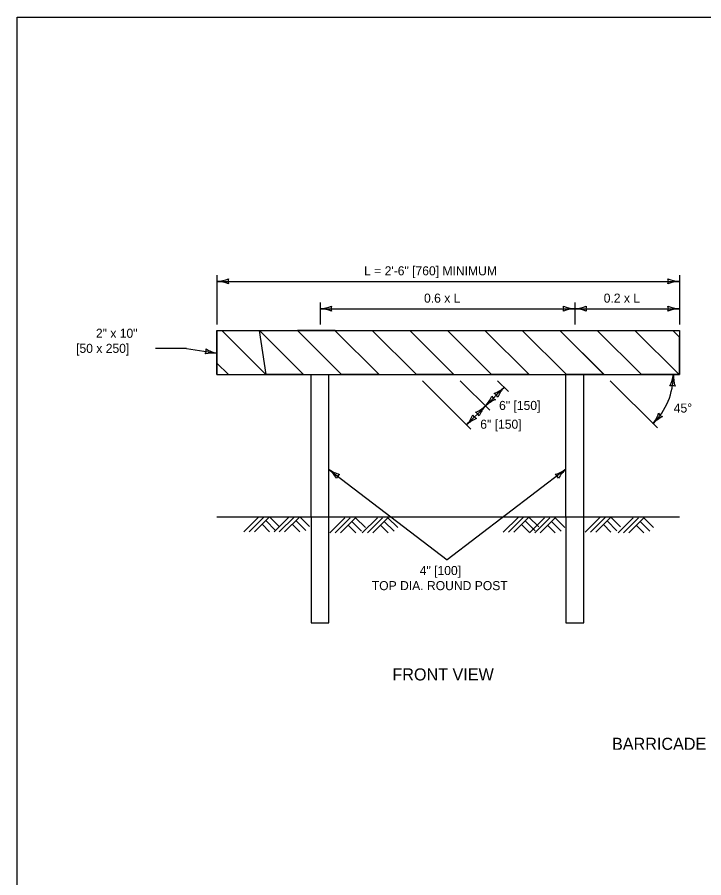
# Model space of a CAD drawing. Extents: x 49991.4 to 50021, y 49987.6 to 50011.4.
# Drawn here: x 49999.38 to 50003.93, y 49993.3 to 49999 of the extents above; entities that cross this region are included whole.
import ezdxf

# ---------------------------------------------------------------- set-up
doc = ezdxf.new("R2010")
doc.units = 0
for name, color, linetype in [('Level 1', 7, 'Continuous'), ('Level 2', 7, 'Continuous'), ('Level 3', 7, 'Continuous'), ('Level 4', 7, 'Continuous')]:
    doc.layers.add(name, color=color, linetype=linetype)

msp = doc.modelspace()

# ---------------------------------------------------------------- linework, layer by layer
at = {"layer": 'Level 1'}
for p, q in [((50000.7069, 49996.9246), (50000.7069, 49996.6317)), ((50000.7069, 49996.7073), (50000.7069, 49996.9246)), ((50000.7069, 49996.9246), (50000.738, 49996.9246)), ((50000.7069, 49996.9246), (50003.7706, 49996.9246)), ((50000.7069, 49996.6317), (50000.7069, 49996.9246)), ((50000.738, 49996.9246), (50000.9865, 49996.9246)), ((50000.738, 49996.9246), (50000.9865, 49996.9246)), ((50000.738, 49996.9246), (50000.9865, 49996.9246)), ((50000.7389, 49996.9246), (50001.031, 49996.6326)), ((50000.7389, 49996.9246), (50001.031, 49996.6326)), ((50001.031, 49996.6326), (50000.7389, 49996.9246)), ((50001.031, 49996.6326), (50000.7389, 49996.9246)), ((50001.031, 49996.6326), (50000.7389, 49996.9246)), ((50001.031, 49996.6326), (50000.7389, 49996.9246)), ((50000.7389, 49996.9246), (50001.031, 49996.6326)), ((50000.9865, 49996.9246), (50001.031, 49996.6326)), ((50000.9879, 49996.9248), (50001.28, 49996.6326)), ((50000.9879, 49996.9248), (50001.28, 49996.6326)), ((50001.2395, 49996.9236), (50001.5316, 49996.6316)), ((50001.2395, 49996.9236), (50001.5316, 49996.6316)), ((50001.5316, 49996.6316), (50001.2395, 49996.9236)), ((50001.5316, 49996.6316), (50001.2395, 49996.9236)), ((50001.2395, 49996.9236), (50001.5316, 49996.6316)), ((50001.489, 49996.9246), (50001.2402, 49996.9246)), ((50001.489, 49996.9246), (50001.2402, 49996.9246)), ((50001.2402, 49996.9246), (50001.489, 49996.9246)), ((50001.4881, 49996.9238), (50001.7802, 49996.6316)), ((50002.0278, 49996.6317), (50001.7353, 49996.9243)), ((50001.7377, 49996.9246), (50001.9842, 49996.9246)), ((50001.9837, 49996.9243), (50002.2731, 49996.6349)), ((50002.5259, 49996.6317), (50002.2333, 49996.9242)), ((50002.2348, 49996.9246), (50002.4817, 49996.9246)), ((50002.4819, 49996.9244), (50002.774, 49996.6322)), ((50003.022, 49996.6319), (50002.7291, 49996.9249)), ((50002.7297, 49996.9246), (50002.9771, 49996.9246)), ((50002.9775, 49996.9249), (50003.2669, 49996.6355)), ((50002.9775, 49996.9249), (50003.2707, 49996.6319)), ((50003.5195, 49996.6317), (50003.2265, 49996.9246)), ((50003.2265, 49996.9246), (50003.4752, 49996.9246)), ((50003.4752, 49996.9246), (50003.7681, 49996.6317)), ((50003.7706, 49996.8802), (50003.7262, 49996.9246)), ((50003.7262, 49996.9246), (50003.7706, 49996.9246)), ((50003.7706, 49996.9246), (50003.7706, 49996.6317)), ((50003.7706, 49996.9246), (50003.7706, 49996.6317)), ((50003.7706, 49996.6317), (50003.7706, 49996.8802)), ((50000.7825, 49996.6317), (50000.7069, 49996.7073)), ((50000.7069, 49996.6355), (50000.7107, 49996.6317)), ((50000.7069, 49996.6317), (50003.7706, 49996.6317)), ((50001.2799, 49996.6317), (50001.0335, 49996.6317)), ((50001.2799, 49996.6317), (50001.0335, 49996.6317)), ((50001.3313, 49995.6901), (50001.3313, 49996.6313)), ((50001.4485, 49995.6901), (50001.4485, 49996.6313)), ((50001.7794, 49996.6317), (50001.5311, 49996.6317)), ((50002.0291, 49996.6317), (50002.0278, 49996.6317)), ((50002.2732, 49996.6317), (50002.0291, 49996.6317)), ((50002.527, 49996.6317), (50002.5259, 49996.6317)), ((50002.7739, 49996.6317), (50002.527, 49996.6317)), ((50003.0188, 49995.6901), (50003.0188, 49996.6311)), ((50003.0224, 49996.6317), (50003.022, 49996.6319)), ((50003.2707, 49996.6317), (50003.0224, 49996.6317)), ((50003.136, 49995.6901), (50003.136, 49996.6311)), ((50003.7681, 49996.6317), (50003.5195, 49996.6317)), ((50000.7069, 49995.6901), (50003.7706, 49995.6901)), ((50000.8849, 49995.5901), (50000.9849, 49995.6901)), ((50000.9199, 49995.5901), (50001.0199, 49995.6901)), ((50000.9549, 49995.5901), (50001.0549, 49995.6901)), ((50001.0302, 49995.6654), (50001.0952, 49995.6004)), ((50001.0549, 49995.6901), (50001.1199, 49995.6251)), ((50001.0849, 49995.5901), (50001.1849, 49995.6901)), ((50001.1199, 49995.5901), (50001.2199, 49995.6901)), ((50001.1549, 49995.5901), (50001.2549, 49995.6901)), ((50001.2302, 49995.6654), (50001.2952, 49995.6004)), ((50001.2549, 49995.6901), (50001.3199, 49995.6251)), ((50001.4547, 49995.5838), (50001.5547, 49995.6838)), ((50001.4897, 49995.5838), (50001.5897, 49995.6838)), ((50001.5247, 49995.5838), (50001.6247, 49995.6838)), ((50001.6, 49995.6591), (50001.665, 49995.5941)), ((50001.6247, 49995.6838), (50001.6897, 49995.6188)), ((50001.6694, 49995.5838), (50001.7694, 49995.6838)), ((50001.7044, 49995.5838), (50001.8044, 49995.6838)), ((50001.7394, 49995.5838), (50001.8394, 49995.6838)), ((50001.8147, 49995.6591), (50001.8797, 49995.5941)), ((50001.8394, 49995.6838), (50001.9044, 49995.6188)), ((50002.6035, 49995.5876), (50002.7035, 49995.6876)), ((50002.6385, 49995.5876), (50002.7385, 49995.6876)), ((50002.6735, 49995.5876), (50002.7735, 49995.6876)), ((50002.7488, 49995.6629), (50002.8138, 49995.5979)), ((50002.7735, 49995.6876), (50002.8385, 49995.6226)), ((50002.7768, 49995.5838), (50002.8768, 49995.6838)), ((50002.8118, 49995.5838), (50002.9118, 49995.6838)), ((50002.8468, 49995.5838), (50002.9468, 49995.6838)), ((50002.9221, 49995.6591), (50002.9871, 49995.5941)), ((50002.9468, 49995.6838), (50003.0118, 49995.6188)), ((50003.1459, 49995.5876), (50003.2459, 49995.6876)), ((50003.1809, 49995.5876), (50003.2809, 49995.6876)), ((50003.2159, 49995.5876), (50003.3159, 49995.6876)), ((50003.2912, 49995.6629), (50003.3562, 49995.5979)), ((50003.3159, 49995.6876), (50003.3809, 49995.6226)), ((50003.3643, 49995.5838), (50003.4643, 49995.6838)), ((50003.3993, 49995.5838), (50003.4993, 49995.6838)), ((50003.4343, 49995.5838), (50003.5343, 49995.6838)), ((50003.5096, 49995.6591), (50003.5746, 49995.5941)), ((50003.5343, 49995.6838), (50003.5993, 49995.6188)), ((50001.0054, 49995.6406), (50001.0559, 49995.5901)), ((50001.2054, 49995.6406), (50001.2559, 49995.5901)), ((50001.5752, 49995.6343), (50001.6257, 49995.5838)), ((50001.7899, 49995.6343), (50001.8404, 49995.5838)), ((50002.724, 49995.6381), (50002.7745, 49995.5876)), ((50002.8973, 49995.6343), (50002.9478, 49995.5838)), ((50003.2664, 49995.6381), (50003.3169, 49995.5876)), ((50003.4848, 49995.6343), (50003.5353, 49995.5838))]:
    msp.add_line(p, q, dxfattribs=at)
msp.add_lwpolyline([(49999.3835, 49998.9992), (50016.7501, 49998.9992), (50016.7501, 49987.7988), (49999.3835, 49987.7988)], close=True, dxfattribs=at)
at = {"layer": 'Level 3'}
for p, q in [((50000.7069, 49997.2895), (50000.7069, 49996.9646)), ((50003.7706, 49997.2895), (50003.7706, 49996.9646)), ((50000.7069, 49997.2495), (50003.7706, 49997.2495)), ((50001.39, 49997.1085), (50001.39, 49996.9646)), ((50003.0775, 49997.1085), (50003.0775, 49996.9646)), ((50001.39, 49997.0685), (50003.0775, 49997.0685)), ((50003.0775, 49997.0685), (50003.7706, 49997.0685)), ((50000.506, 49996.8058), (50000.2987, 49996.8058)), ((50000.506, 49996.8058), (50000.7069, 49996.7734)), ((50002.3886, 49996.271), (50002.0679, 49996.5917)), ((50002.5135, 49996.3957), (50002.3175, 49996.5917)), ((50002.6379, 49996.5198), (50002.566, 49996.5917)), ((50003.6243, 49996.2784), (50003.311, 49996.5917)), ((50002.6097, 49996.548), (50002.4853, 49996.4239)), ((50002.4853, 49996.4239), (50002.3603, 49996.2993)), ((50001.4485, 49996.004), (50002.2324, 49995.4042)), ((50003.0188, 49996.0045), (50002.2324, 49995.4042))]:
    msp.add_line(p, q, dxfattribs=at)
for centre, radius, start, end in [((50000.6954, 49997.4822), 0.233, 272.8273, 292.0772), ((50000.8351, 49997.2495), 0.0548, 162.1388, 197.8612), ((50003.7798, 49997.4716), 0.2223, 247.456, 267.6395), ((50003.6424, 49997.2495), 0.0548, 342.1388, 17.8612), ((50000.6977, 49997.0274), 0.2223, 67.456, 87.6395), ((50003.7821, 49997.0168), 0.233, 92.8273, 112.0772), ((50001.3785, 49997.3012), 0.233, 272.8273, 292.0772), ((50001.5182, 49997.0685), 0.0548, 162.1388, 197.8612), ((50003.0867, 49997.2906), 0.2223, 247.456, 267.6395), ((50002.9493, 49997.0685), 0.0548, 342.1388, 17.8612), ((50003.066, 49997.3012), 0.233, 272.8273, 292.0772), ((50003.2057, 49997.0685), 0.0548, 162.1388, 197.8612), ((50003.7798, 49997.2906), 0.2223, 247.456, 267.6395), ((50003.6424, 49997.0685), 0.0548, 342.1388, 17.8612), ((50001.3808, 49996.8464), 0.2223, 67.456, 87.6395), ((50003.089, 49996.8358), 0.233, 92.8273, 112.0772), ((50003.0683, 49996.8464), 0.2223, 67.456, 87.6395), ((50003.7821, 49996.8358), 0.233, 92.8273, 112.0772), ((50000.5803, 49996.7938), 0.0548, 332.971, 8.6933), ((50000.7513, 49996.9912), 0.2223, 238.2881, 258.4717), ((50000.6812, 49996.5418), 0.233, 83.6594, 102.9093), ((50003.2709, 49996.6317), 0.4597, 315.0111, 0), ((50003.5099, 49996.6586), 0.2223, 332.8744, 353.0579), ((50003.9635, 49996.6246), 0.233, 178.2457, 197.4956), ((50002.4593, 49996.7118), 0.2223, 292.3868, 312.5704), ((50002.7821, 49996.3914), 0.233, 137.7581, 157.008), ((50003.7204, 49996.5039), 0.0548, 67.5572, 103.2796), ((50002.3128, 49996.5806), 0.233, 317.7581, 337.008), ((50002.6356, 49996.2602), 0.2223, 112.3868, 132.5703), ((50002.576, 49996.5145), 0.0548, 207.0697, 242.792), ((50002.5189, 49996.4575), 0.0548, 27.0697, 62.792), ((50002.3349, 49996.5877), 0.2223, 292.3868, 312.5704), ((50002.6577, 49996.2673), 0.233, 137.7581, 157.008), ((50002.1878, 49996.4559), 0.233, 317.7581, 337.008), ((50002.5107, 49996.1356), 0.2223, 112.3868, 132.5703), ((50002.4511, 49996.3899), 0.0548, 207.0697, 242.792), ((50002.3945, 49996.3334), 0.0548, 27.0697, 62.792), ((50003.4113, 49996.4487), 0.233, 322.4498, 341.6996), ((50003.7593, 49996.1558), 0.2223, 117.0785, 137.262), ((50003.6791, 49996.4044), 0.0548, 211.7613, 247.4837), ((50001.3062, 49995.8331), 0.2223, 30.0358, 50.2193), ((50001.5808, 49996.1958), 0.233, 235.4071, 254.6569), ((50002.8913, 49996.1866), 0.2223, 284.8164, 304.9999), ((50003.1692, 49995.8265), 0.233, 130.1877, 149.4375), ((50001.5503, 49995.9261), 0.0548, 124.7186, 160.4409), ((50002.9169, 49995.9267), 0.0548, 19.4992, 55.2216)]:
    msp.add_arc(centre, radius, start, end, dxfattribs=at)
at = {"layer": 'Level 4'}
for p, q in [((50001.3313, 49995.6901), (50001.3313, 49994.987)), ((50001.4485, 49994.987), (50001.4485, 49995.6901)), ((50003.0188, 49995.6901), (50003.0188, 49994.987)), ((50003.136, 49994.987), (50003.136, 49995.6901)), ((50001.3313, 49994.987), (50001.4485, 49994.987)), ((50003.0188, 49994.987), (50003.136, 49994.987))]:
    msp.add_line(p, q, dxfattribs=at)

# ---------------------------------------------------------------- texts
at = {"layer": 'Level 2'}
for s, height, p in [('L = 2\'-6" [760] MINIMUM', 0.06, (50001.6816, 49997.2895)), ('0.6 x L', 0.06, (50002.0785, 49997.1085)), ('0.2 x L', 0.06, (50003.2688, 49997.1085)), ('2" x 10"', 0.06, (49999.9049, 49996.8758)), ('[50 x 250]', 0.06, (49999.7737, 49996.7758)), ('45°', 0.06, (50003.7326, 49996.3805)), ('4" [100]', 0.06, (50002.05, 49995.3042)), ('TOP DIA. ROUND POST', 0.06, (50001.7324, 49995.2042)), ('FRONT VIEW', 0.08, (50001.8691, 49994.6062)), ('BARRICADE DETAILS', 0.08, (50003.324, 49994.1466))]:
    msp.add_text(s, height=height, dxfattribs=at).set_placement(p)
for p in [(50002.5757, 49996.3977), (50002.451, 49996.2733)]:
    msp.add_text('6" [150]', height=0.06, rotation=360, dxfattribs=at).set_placement(p)

doc.saveas('drawing.dxf')
